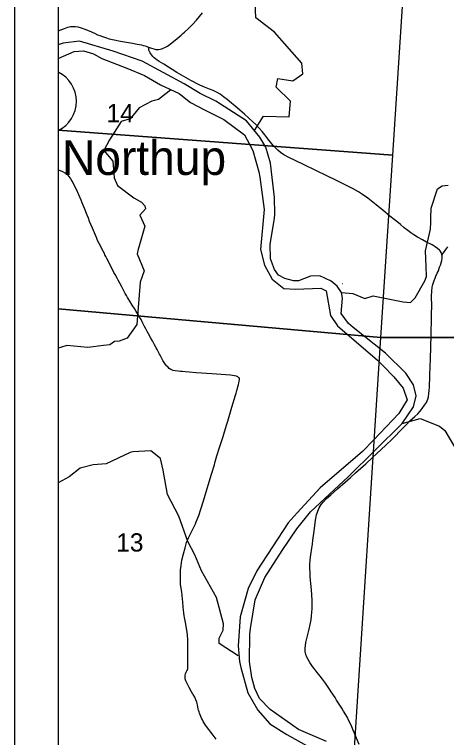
# Model space of a CAD drawing. Extents: x 21.4 to 65.3, y 4 to 26.
# Drawn here: x 23.447 to 24.436, y 20.591 to 22.248 of the extents above; entities that cross this region are included whole.
import ezdxf

# ---------------------------------------------------------------- set-up
doc = ezdxf.new("R2010")
doc.units = 0
for name, color, linetype in [('Default', 7, 'Continuous'), ('GM_X_County_Road', 7, 'Continuous'), ('GM_X_Major_River', 7, 'Continuous'), ('GM_X_Minor_River', 7, 'Continuous'), ('GM_X_Section', 7, 'Continuous'), ('GM_X_Section_Text', 7, 'Continuous'), ('GM_X_Township_Road', 7, 'Continuous'), ('GM_X_Unincorporated_Text', 7, 'Continuous'), ('SH_Cut_Line', 7, 'Continuous'), ('SH_Data', 7, 'Continuous')]:
    doc.layers.add(name, color=color, linetype=linetype)

msp = doc.modelspace()

# ---------------------------------------------------------------- linework, layer by layer
at = {"layer": 'Default'}
msp.add_line((23.5473, 22.1159), (23.5473, 21.9821), dxfattribs=at)
msp.add_lwpolyline([(23.5473, 24.8542), (23.5473, 20.5568), (23.9671, 20.5321), (24.2595, 20.5181), (24.9947, 20.491), (25.2828, 20.4818), (25.7909, 20.4519), (25.8002, 20.4525), (25.809, 20.4526), (25.8187, 20.4522), (25.831, 20.4509), (25.8341, 20.4506), (25.8391, 20.4499), (25.8459, 20.4493), (25.8552, 20.4488), (25.869, 20.4484), (25.878, 20.4484)], dxfattribs=at)
for points in [[(23.5473, 22.3957), (23.5473, 21.9832), (24.3136, 21.9252), (24.3404, 22.3383)], [(23.5473, 21.9832), (23.5473, 21.5732), (24.2858, 21.5075), (24.3136, 21.9252)], [(23.5473, 21.5732), (23.5473, 20.5578), (24.2227, 20.5192), (24.2858, 21.5075)]]:
    msp.add_lwpolyline(points, close=True, dxfattribs=at)
msp.add_arc((23.5147, 22.049), 0.0744, 295.9707, 64.0293, dxfattribs=at)
at = {"layer": 'GM_X_County_Road'}
for points in [[(23.5473, 22.2106), (23.5617, 22.2162), (23.5693, 22.2188), (23.5752, 22.2202), (23.5806, 22.2208), (23.5867, 22.2205), (23.5927, 22.2195), (23.5998, 22.2176), (23.6085, 22.2144), (23.6181, 22.2102), (23.6303, 22.2049), (23.6375, 22.2017), (23.6427, 22.1997), (23.6485, 22.1974), (23.6556, 22.1949), (23.6639, 22.1924), (23.6757, 22.1897), (23.6902, 22.187), (23.7171, 22.1821), (23.7281, 22.1803), (23.7333, 22.1793), (23.7384, 22.1784), (23.7422, 22.1773), (23.7461, 22.1763), (23.7502, 22.1747), (23.7541, 22.1733), (23.7608, 22.1708), (23.7664, 22.169), (23.771, 22.1677), (23.7741, 22.1675), (23.7772, 22.1676), (23.781, 22.1682), (23.7849, 22.1694), (23.788, 22.1706), (23.7913, 22.1721), (23.7973, 22.1756), (23.804, 22.1802), (23.8195, 22.1928), (23.8289, 22.2009), (23.8325, 22.2042), (23.8366, 22.2078), (23.8462, 22.2164), (23.8551, 22.2251), (23.864, 22.2347), (23.8712, 22.2433), (23.8774, 22.2519)], [(24.2363, 20.5747), (24.2227, 20.6076), (24.2192, 20.6154), (24.2154, 20.6241), (24.2122, 20.6309), (24.2094, 20.6364), (24.2058, 20.643), (24.2006, 20.6515), (24.1967, 20.6578), (24.1877, 20.672), (24.1847, 20.6767), (24.181, 20.6824), (24.1726, 20.6955), (24.1699, 20.6996), (24.1589, 20.7154), (24.1526, 20.7243), (24.147, 20.7314), (24.1439, 20.7353), (24.1405, 20.7397), (24.1354, 20.7458), (24.1318, 20.7502), (24.1276, 20.7563), (24.1233, 20.7626), (24.1193, 20.7694), (24.1166, 20.7753), (24.1143, 20.7814), (24.113, 20.7878), (24.1127, 20.7946), (24.1132, 20.8017), (24.1142, 20.809), (24.1165, 20.8181), (24.1215, 20.8389), (24.1238, 20.8497), (24.1261, 20.8608), (24.1272, 20.8688), (24.1283, 20.8779), (24.1285, 20.886), (24.1286, 20.894), (24.1286, 20.904), (24.1277, 20.9183), (24.1272, 20.9282), (24.1256, 20.9449), (24.1251, 20.9511), (24.1242, 20.961), (24.1238, 20.9703), (24.1234, 20.9777), (24.1235, 20.9876), (24.1242, 20.9981), (24.1256, 21.0092), (24.1279, 21.0245), (24.1295, 21.0343), (24.1306, 21.0429), (24.1332, 21.064), (24.1367, 21.0893), (24.1388, 21.1011), (24.1414, 21.1098), (24.1446, 21.1175), (24.1497, 21.1249), (24.1544, 21.1309), (24.1619, 21.1386), (24.1713, 21.1468), (24.1869, 21.161), (24.2042, 21.176), (24.2163, 21.1868), (24.2281, 21.1974), (24.2518, 21.2179), (24.2672, 21.2324), (24.2763, 21.2408), (24.2976, 21.2607), (24.3119, 21.2746), (24.3201, 21.2831), (24.3279, 21.2911), (24.3356, 21.2992), (24.3443, 21.308), (24.3525, 21.3163), (24.3634, 21.3264), (24.3708, 21.3327), (24.376, 21.3385), (24.3808, 21.3451), (24.3858, 21.3523), (24.3902, 21.3589), (24.392, 21.3629), (24.3933, 21.3664), (24.3948, 21.3717), (24.3959, 21.379), (24.3966, 21.3863), (24.3971, 21.3938), (24.3975, 21.4018), (24.3978, 21.4117), (24.3979, 21.4161), (24.3982, 21.4241), (24.3986, 21.4384), (24.3995, 21.4608), (24.4003, 21.4831), (24.4006, 21.4937), (24.4009, 21.5052), (24.4014, 21.5228), (24.402, 21.5445), (24.4021, 21.5551), (24.4021, 21.5638), (24.4024, 21.5781), (24.4022, 21.6034), (24.4026, 21.612), (24.4029, 21.6169), (24.4033, 21.62), (24.4037, 21.623), (24.4045, 21.626), (24.4052, 21.6289), (24.4065, 21.6337), (24.4083, 21.6383), (24.4102, 21.6435), (24.412, 21.6481), (24.415, 21.6553), (24.4168, 21.6593), (24.4184, 21.6635), (24.4204, 21.6687), (24.4223, 21.6733), (24.424, 21.6786), (24.4256, 21.684), (24.4262, 21.6884), (24.4263, 21.6909), (24.4262, 21.6947), (24.4257, 21.6968), (24.4253, 21.699), (24.424, 21.7026), (24.4216, 21.7063), (24.4199, 21.7082), (24.4157, 21.712), (24.4106, 21.7157), (24.4036, 21.7198), (24.3908, 21.7264), (24.3815, 21.7312), (24.3701, 21.7375), (24.3617, 21.7427), (24.3546, 21.7477), (24.3476, 21.7529), (24.3394, 21.7594), (24.3308, 21.7665), (24.3226, 21.7732), (24.3136, 21.7805), (24.3057, 21.7869), (24.2915, 21.7985), (24.2749, 21.8121), (24.2559, 21.8271), (24.2443, 21.8355), (24.2348, 21.8416), (24.2224, 21.8487), (24.2075, 21.8564), (24.1817, 21.8688), (24.1638, 21.8775), (24.1359, 21.891), (24.1107, 21.9032), (24.0899, 21.913), (24.0755, 21.9203), (24.0641, 21.9266), (24.0564, 21.9318), (24.0502, 21.9368), (24.044, 21.9429), (24.0403, 21.9471), (24.0366, 21.9512), (24.0304, 21.9592), (24.0252, 21.9659), (24.0201, 21.9723), (24.014, 21.9801), (24.0075, 21.9876), (23.9997, 21.9956), (23.9924, 22.0024), (23.9838, 22.0105), (23.974, 22.0192), (23.9633, 22.0287), (23.9515, 22.0388), (23.9439, 22.0451), (23.9342, 22.0529), (23.9259, 22.0595), (23.9178, 22.0653), (23.9097, 22.0701), (23.9025, 22.0736), (23.8938, 22.0771), (23.8822, 22.0815), (23.8719, 22.0859), (23.8669, 22.0882), (23.8636, 22.0899), (23.8571, 22.0933), (23.8509, 22.097), (23.8188, 22.1154), (23.7891, 22.1338), (23.7784, 22.1405), (23.7739, 22.1435), (23.7701, 22.1463), (23.7671, 22.1489), (23.7642, 22.1517), (23.7617, 22.1544), (23.7596, 22.1575), (23.7577, 22.1603), (23.7562, 22.1632), (23.7551, 22.1664), (23.7545, 22.1695), (23.7541, 22.1733)]]:
    msp.add_lwpolyline(points, dxfattribs=at)
at = {"layer": 'GM_X_Major_River'}
for points in [[(24.0431, 21.79), (24.0422, 21.8283), (24.0333, 21.9076), (24.0229, 21.9436), (24.0089, 21.9671), (23.9788, 22.0045), (23.9082, 22.0494), (23.8722, 22.0671), (23.8358, 22.0894), (23.7398, 22.1407), (23.673, 22.1639), (23.5965, 22.1872), (23.5586, 22.1821), (23.5473, 22.1786)], [(23.5473, 22.1472), (23.5836, 22.1632), (23.6056, 22.1644), (23.628, 22.1577), (23.6469, 22.1471), (23.7046, 22.1246), (23.7452, 22.1084), (23.7816, 22.0869), (23.8241, 22.0666), (23.8503, 22.0466), (23.8825, 22.0292), (23.9265, 22.0074), (23.974, 21.9723), (23.993, 21.9363), (24.0068, 21.887), (24.0091, 21.8752), (24.0188, 21.8013), (24.0107, 21.709), (24.0199, 21.6738), (24.0374, 21.6416), (24.0636, 21.6201), (24.0909, 21.6183), (24.1485, 21.6207), (24.1606, 21.6147), (24.1707, 21.5578), (24.187, 21.5344), (24.2785, 21.4561), (24.2911, 21.4425), (24.3158, 21.4179), (24.3367, 21.3915), (24.3462, 21.3645), (24.327, 21.3334), (24.2692, 21.2721), (24.2443, 21.2462), (24.1472, 21.1635), (24.0947, 21.106), (24.0735, 21.0827), (24.0022, 20.9732), (23.9819, 20.9325), (23.9643, 20.8672), (23.9595, 20.8008), (23.9623, 20.7651), (23.9654, 20.7515), (23.9818, 20.6931), (24.0047, 20.6537), (24.032, 20.6219), (24.0704, 20.5978), (24.1553, 20.5506)], [(24.1613, 20.5814), (24.0972, 20.6092), (24.0323, 20.6549), (24.008, 20.6806), (23.9977, 20.703), (23.9904, 20.7288), (23.985, 20.7652), (23.9864, 20.8278), (23.9875, 20.8407), (23.9983, 20.9068), (24.0205, 20.9573), (24.0604, 21.0193), (24.0936, 21.0695), (24.125, 21.108), (24.2115, 21.1884), (24.3346, 21.3102), (24.3607, 21.3487), (24.3667, 21.3741), (24.3605, 21.3995), (24.343, 21.4256), (24.2967, 21.4718), (24.2226, 21.5307), (24.212, 21.5401), (24.1953, 21.5628), (24.1978, 21.5978), (24.1959, 21.6107), (24.186, 21.625), (24.1723, 21.6371), (24.1465, 21.6488), (24.1246, 21.6484), (24.0977, 21.6373), (24.0863, 21.6376), (24.0662, 21.6428), (24.0518, 21.6504), (24.0427, 21.6636), (24.0335, 21.6882), (24.0323, 21.7216), (24.0427, 21.7805), (24.0431, 21.79)]]:
    msp.add_lwpolyline(points, dxfattribs=at)
at = {"layer": 'GM_X_Minor_River'}
for points in [[(23.9968, 21.982), (24.0176, 22.0153), (24.076, 22.0132), (24.0794, 22.0496), (24.0463, 22.0816), (24.0502, 22.1014), (24.0848, 22.0956), (24.1074, 22.1121), (24.1052, 22.1364), (24.0424, 22.2076), (23.9998, 22.2402), (23.9934, 22.3787)], [(23.8049, 22.075), (23.7768, 22.0531), (23.7617, 22.0493), (23.7325, 22.0344), (23.712, 22.0086), (23.6915, 22.0028), (23.6646, 21.9606), (23.6517, 21.9363), (23.6725, 21.9119), (23.6752, 21.8735), (23.6835, 21.8561), (23.7203, 21.828), (23.7377, 21.8181), (23.746, 21.8094), (23.7472, 21.8029), (23.7339, 21.7881), (23.746, 21.7626), (23.7316, 21.7147), (23.7304, 21.7101), (23.7282, 21.6995), (23.7445, 21.6603), (23.735, 21.6348), (23.7277, 21.5375), (23.7054, 21.5063), (23.6868, 21.4994), (23.6762, 21.4983), (23.6655, 21.491), (23.6511, 21.4895), (23.6155, 21.4849), (23.567, 21.489), (23.553, 21.4845), (23.5476, 21.4829), (23.5473, 21.4828)], [(24.1959, 21.6107), (24.2221, 21.6087), (24.2494, 21.597), (24.2687, 21.6031), (24.3373, 21.5898), (24.354, 21.5876), (24.3642, 21.5986), (24.387, 21.6378), (24.3904, 21.6473), (24.39, 21.6701), (24.3881, 21.7066), (24.3999, 21.7557), (24.4007, 21.7709), (24.4007, 21.7819), (24.4014, 21.804), (24.4159, 21.8481), (24.4265, 21.8553), (24.4398, 21.8565)], [(24.1711, 21.6415), (24.1711, 21.6415)], [(24.1715, 21.6413), (24.1715, 21.6413)], [(24.1978, 21.6308), (24.1977, 21.6308)], [(24.3346, 21.3102), (24.3759, 21.3218), (24.4202, 21.3048), (24.4323, 21.2949), (24.4744, 21.2238), (24.4835, 21.1965), (24.4941, 21.1269), (24.4922, 21.0756), (24.4937, 21.0216), (24.483, 20.9824), (24.4743, 20.9292), (24.4826, 20.8824), (24.4974, 20.8189)], [(23.9594, 20.7779), (23.9155, 20.8062), (23.9162, 20.8187), (23.925, 20.837), (23.9257, 20.8514), (23.9095, 20.9115), (23.8754, 20.9726), (23.8602, 21.0099), (23.8439, 21.0403), (23.8235, 21.0984), (23.7977, 21.1482), (23.7879, 21.2037), (23.7818, 21.2303), (23.7595, 21.2478), (23.7185, 21.2459), (23.7125, 21.2439), (23.6571, 21.2184), (23.6272, 21.2157), (23.5976, 21.2085), (23.5726, 21.1883), (23.5473, 21.1744)]]:
    msp.add_lwpolyline(points, dxfattribs=at)
at = {"layer": 'GM_X_Section'}
for points in [[(24.3505, 22.5376), (24.828, 22.5152), (25.4085, 22.5025), (25.3384, 21.4821), (24.7985, 21.5074), (24.2858, 21.5075), (24.3136, 21.9252), (24.3404, 22.3383)], [(25.3384, 21.4821), (25.275, 20.4836), (24.2227, 20.5192), (24.2858, 21.5075), (24.7985, 21.5074)]]:
    msp.add_lwpolyline(points, close=True, dxfattribs=at)
at = {"layer": 'GM_X_Township_Road'}
for points in [[(23.961, 21.4032), (23.962, 21.4073), (23.9623, 21.4103), (23.9621, 21.4127), (23.9613, 21.4149), (23.9604, 21.4163), (23.9585, 21.4177), (23.9553, 21.419), (23.951, 21.4199), (23.9418, 21.4211), (23.899, 21.4241), (23.8635, 21.4269), (23.8475, 21.4282), (23.8383, 21.4289), (23.831, 21.4294), (23.8272, 21.4298), (23.8219, 21.4304), (23.8155, 21.4314), (23.8106, 21.4324), (23.8055, 21.4345), (23.8016, 21.4369), (23.7983, 21.4401), (23.7961, 21.4423), (23.7932, 21.4457), (23.7914, 21.4482), (23.79, 21.4502), (23.7887, 21.4523), (23.7871, 21.455), (23.7848, 21.4593), (23.7821, 21.4643), (23.7806, 21.467), (23.7795, 21.4692), (23.7761, 21.4757), (23.7736, 21.4805), (23.7716, 21.4843), (23.7682, 21.4909), (23.7664, 21.4941), (23.7629, 21.5), (23.7595, 21.5058), (23.7538, 21.5161), (23.751, 21.5216), (23.7479, 21.5277), (23.7452, 21.5332), (23.7429, 21.5377), (23.7399, 21.5433), (23.7371, 21.5487), (23.7338, 21.5543), (23.7302, 21.5605), (23.7258, 21.5675), (23.7217, 21.574), (23.7168, 21.582), (23.7114, 21.591), (23.7076, 21.5974), (23.7063, 21.5996), (23.7037, 21.6041), (23.701, 21.6088), (23.6969, 21.6163), (23.6927, 21.624), (23.6884, 21.6319), (23.6847, 21.6387), (23.682, 21.6436), (23.6777, 21.6518), (23.6751, 21.6567), (23.6709, 21.6651), (23.6665, 21.6738), (23.6616, 21.6831), (23.6589, 21.6886), (23.6566, 21.693), (23.6544, 21.6974), (23.653, 21.7002), (23.6501, 21.7057), (23.6473, 21.7112), (23.6447, 21.7165), (23.6413, 21.7234), (23.6377, 21.7302), (23.6349, 21.7367), (23.6304, 21.7477), (23.6258, 21.7585), (23.6223, 21.7665), (23.6194, 21.7736), (23.6164, 21.7809), (23.6138, 21.7877), (23.6122, 21.7919), (23.6084, 21.8017), (23.6041, 21.8127), (23.6025, 21.8167), (23.6001, 21.8225), (23.5946, 21.8349), (23.5891, 21.8465), (23.5857, 21.8535), (23.5822, 21.8609), (23.5794, 21.8662), (23.5773, 21.8696), (23.5753, 21.8731), (23.5719, 21.8774), (23.568, 21.8813), (23.5635, 21.8845), (23.5581, 21.8875), (23.5525, 21.8898), (23.5473, 21.8913)], [(24.4257, 21.6968), (24.4319, 21.7051), (24.4349, 21.7091), (24.4393, 21.7151)], [(23.8558, 20.6901), (23.8524, 20.6956), (23.8471, 20.7052), (23.8424, 20.7145), (23.8395, 20.721), (23.8384, 20.7253), (23.8381, 20.7297), (23.8383, 20.7341), (23.839, 20.7372), (23.8404, 20.7408), (23.8419, 20.7435), (23.843, 20.7457), (23.844, 20.7485), (23.8444, 20.7521), (23.8445, 20.7589), (23.8443, 20.7694), (23.8442, 20.7775), (23.8442, 20.7874), (23.844, 20.8141), (23.8433, 20.8259), (23.842, 20.8369), (23.8388, 20.8546), (23.8368, 20.8656), (23.836, 20.8704), (23.8352, 20.8755), (23.8344, 20.8832), (23.8337, 20.8897), (23.8327, 20.9015), (23.8322, 20.9082), (23.8312, 20.9174), (23.8305, 20.923), (23.8297, 20.9284), (23.8291, 20.9328), (23.8284, 20.9373), (23.8277, 20.9421), (23.8272, 20.9526), (23.8271, 20.9647), (23.8275, 20.9754), (23.8286, 20.9854), (23.8306, 20.9971), (23.8343, 21.0118), (23.8379, 21.0258), (23.8397, 21.032), (23.8414, 21.0379), (23.8436, 21.0435), (23.8457, 21.0489), (23.8499, 21.058), (23.8613, 21.0808), (23.8632, 21.0849), (23.8657, 21.0903), (23.8673, 21.0947), (23.8691, 21.0996), (23.879, 21.131), (23.8983, 21.1946), (23.9049, 21.216), (23.9063, 21.2207), (23.9078, 21.2261), (23.9108, 21.2362), (23.9174, 21.2576), (23.9204, 21.267), (23.9247, 21.2806), (23.9263, 21.2859), (23.9327, 21.3066), (23.9355, 21.3162), (23.9389, 21.3268), (23.9447, 21.3477), (23.9531, 21.3757), (23.9544, 21.3799), (23.9562, 21.3865), (23.9603, 21.4001), (23.961, 21.4032)], [(23.9088, 20.5871), (23.9022, 20.5962), (23.8969, 20.603), (23.892, 20.6094), (23.8869, 20.6158), (23.8844, 20.6195), (23.882, 20.623), (23.8796, 20.6273), (23.8774, 20.6312), (23.8755, 20.6352), (23.8736, 20.639), (23.8708, 20.6466), (23.8699, 20.6497), (23.8689, 20.6532), (23.8681, 20.6567), (23.8673, 20.6605), (23.8661, 20.666), (23.8644, 20.6719), (23.8624, 20.6774), (23.8598, 20.6832), (23.8563, 20.6892), (23.8558, 20.6901)]]:
    msp.add_lwpolyline(points, dxfattribs=at)
at = {"layer": 'SH_Cut_Line'}
msp.add_lwpolyline([(23.5473, 24.8542), (23.5473, 18.0542), (28.6177, 18.0542)], dxfattribs=at)
at = {"layer": 'SH_Data'}
for p, q in [((23.4473, 24.9542), (23.4473, 17.9542)), ((23.5473, 24.8542), (23.5473, 18.0542))]:
    msp.add_line(p, q, dxfattribs=at)

# ---------------------------------------------------------------- texts
at = {"layer": 'GM_X_Section_Text'}
for s, p in [('14', (23.6582, 22.0011)), ('13', (23.6803, 21.0171))]:
    msp.add_text(s, height=0.04186, rotation=0, dxfattribs=at).set_placement(p)
at = {"layer": 'GM_X_Unincorporated_Text'}
msp.add_text('Northup', height=0.07898, rotation=0, dxfattribs=at).set_placement((23.5561, 21.8803))

doc.saveas('drawing.dxf')
